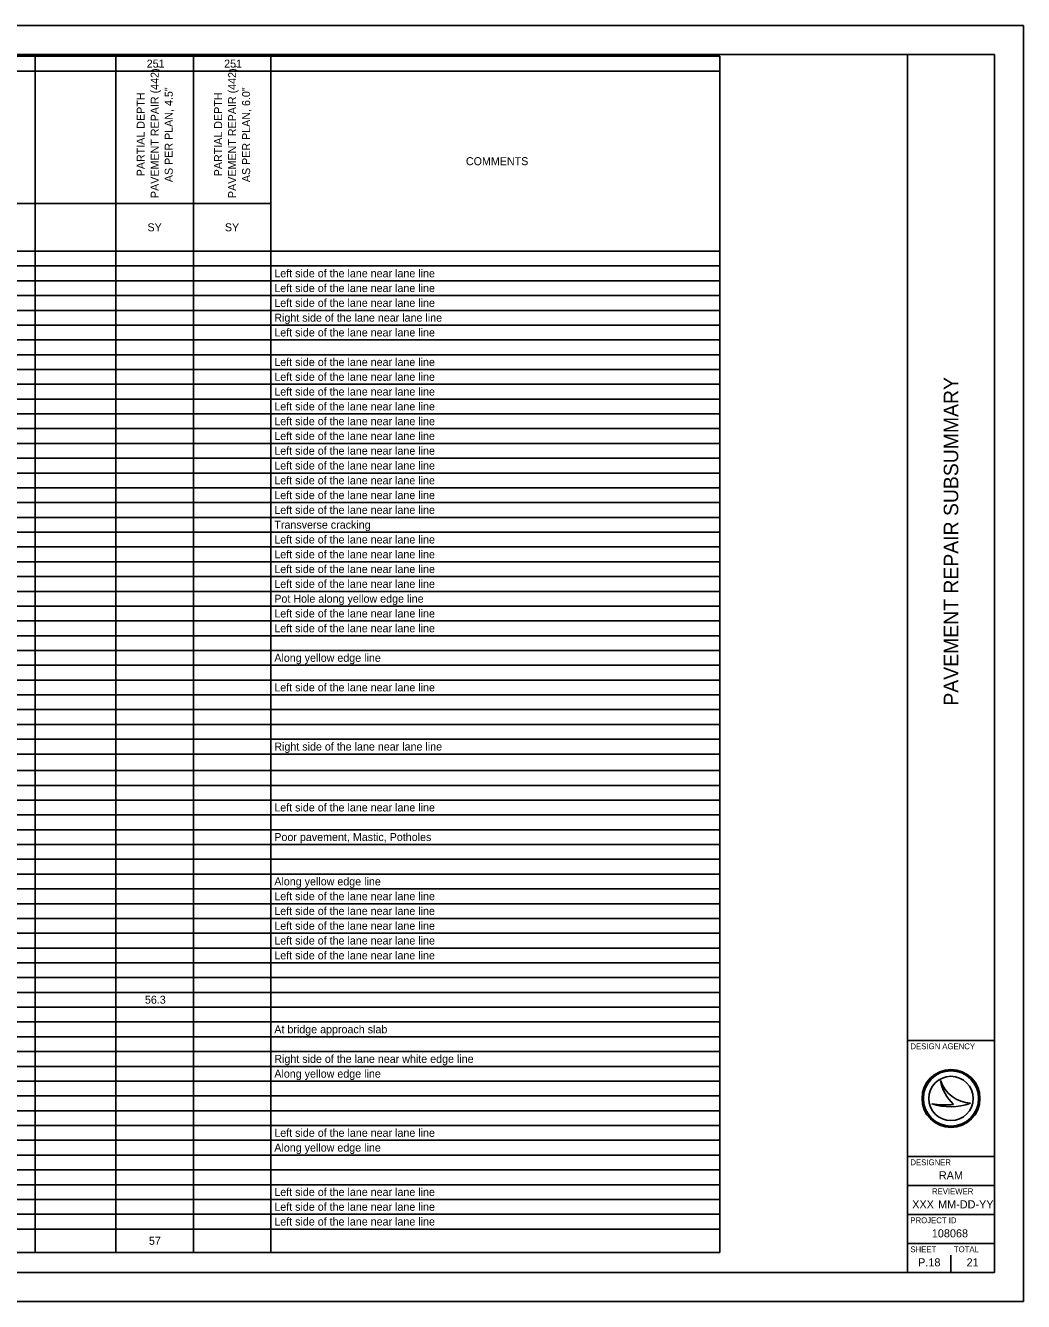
# Model space of a CAD drawing. Extents: x 0 to 34, y 0 to 22.
# Drawn here: x 16.79 to 34, y 0 to 22 of the extents above; entities that cross this region are included whole.
import ezdxf

# ---------------------------------------------------------------- set-up
doc = ezdxf.new("R2010")
doc.units = 0
for name, color, linetype in [('Default', 7, 'Continuous'), ('SH_Border', 7, 'Continuous'), ('SH_Cut_Line', 7, 'Continuous'), ('SH_Data', 7, 'Continuous')]:
    doc.layers.add(name, color=color, linetype=linetype)

msp = doc.modelspace()

# ---------------------------------------------------------------- linework, layer by layer
at = {"layer": 'Default'}
for p, q in [((4.701, 21.469), (28.761, 21.469)), ((16.956, 21.469), (16.956, 0.844)), ((18.351, 21.469), (18.351, 0.844)), ((19.686, 21.469), (19.686, 0.844)), ((21.021, 21.469), (21.021, 0.844)), ((28.761, 21.469), (28.761, 0.844)), ((4.701, 21.214), (28.761, 21.214)), ((7.806, 18.934), (21.021, 18.934)), ((4.701, 18.109), (28.761, 18.109)), ((4.701, 17.854), (28.761, 17.854)), ((4.701, 17.599), (28.761, 17.599)), ((4.701, 17.344), (28.761, 17.344)), ((4.701, 17.089), (28.761, 17.089)), ((4.701, 16.834), (28.761, 16.834)), ((4.701, 16.579), (28.761, 16.579)), ((4.701, 16.324), (28.761, 16.324)), ((4.701, 16.069), (28.761, 16.069)), ((4.701, 15.814), (28.761, 15.814)), ((4.701, 15.559), (28.761, 15.559)), ((4.701, 15.304), (28.761, 15.304)), ((4.701, 15.049), (28.761, 15.049)), ((4.701, 14.794), (28.761, 14.794)), ((4.701, 14.539), (28.761, 14.539)), ((4.701, 14.284), (28.761, 14.284)), ((4.701, 14.029), (28.761, 14.029)), ((4.701, 13.774), (28.761, 13.774)), ((4.701, 13.519), (28.761, 13.519)), ((4.701, 13.264), (28.761, 13.264)), ((4.701, 13.009), (28.761, 13.009)), ((4.701, 12.754), (28.761, 12.754)), ((4.701, 12.499), (28.761, 12.499)), ((4.701, 12.244), (28.761, 12.244)), ((4.701, 11.989), (28.761, 11.989)), ((4.701, 11.734), (28.761, 11.734)), ((4.701, 11.479), (28.761, 11.479)), ((4.701, 11.224), (28.761, 11.224)), ((4.701, 10.969), (28.761, 10.969)), ((4.701, 10.714), (28.761, 10.714)), ((4.701, 10.459), (28.761, 10.459)), ((4.701, 10.204), (28.761, 10.204)), ((4.701, 9.949), (28.761, 9.949)), ((4.701, 9.694), (28.761, 9.694)), ((4.701, 9.439), (28.761, 9.439)), ((4.701, 9.154), (28.761, 9.154)), ((4.701, 8.899), (28.761, 8.899)), ((4.701, 8.644), (28.761, 8.644)), ((4.701, 8.389), (28.761, 8.389)), ((4.701, 8.134), (28.761, 8.134)), ((4.701, 7.879), (28.761, 7.879)), ((4.701, 7.624), (28.761, 7.624)), ((4.701, 7.369), (28.761, 7.369)), ((4.701, 7.114), (28.761, 7.114)), ((4.701, 6.859), (28.761, 6.859)), ((4.701, 6.604), (28.761, 6.604)), ((4.701, 6.349), (28.761, 6.349)), ((4.701, 6.094), (28.761, 6.094)), ((4.701, 5.839), (28.761, 5.839)), ((4.701, 5.584), (28.761, 5.584)), ((4.701, 5.329), (28.761, 5.329)), ((4.701, 5.074), (28.761, 5.074)), ((4.701, 4.819), (28.761, 4.819)), ((4.701, 4.564), (28.761, 4.564)), ((4.701, 4.309), (28.761, 4.309)), ((4.701, 4.054), (28.761, 4.054)), ((4.701, 3.799), (28.761, 3.799)), ((4.701, 3.544), (28.761, 3.544)), ((4.701, 3.289), (28.761, 3.289)), ((4.701, 3.034), (28.761, 3.034)), ((4.701, 2.779), (28.761, 2.779)), ((4.701, 2.524), (28.761, 2.524)), ((4.701, 2.269), (28.761, 2.269)), ((4.701, 2.014), (28.761, 2.014)), ((4.701, 1.759), (28.761, 1.759)), ((4.701, 1.504), (28.761, 1.504)), ((4.701, 1.249), (28.761, 1.249)), ((4.701, 0.844), (28.761, 0.844))]:
    msp.add_line(p, q, dxfattribs=at)
for points in [[(21.021, 14.284), (28.761, 14.284), (28.761, 14.029), (21.021, 14.029)], [(21.021, 13.519), (28.761, 13.519), (28.761, 13.264), (21.021, 13.264)], [(21.021, 13.264), (28.761, 13.264), (28.761, 13.009), (21.021, 13.009)], [(21.021, 13.009), (28.761, 13.009), (28.761, 12.754), (21.021, 12.754)], [(21.021, 12.499), (28.761, 12.499), (28.761, 12.244), (21.021, 12.244)], [(21.021, 12.244), (28.761, 12.244), (28.761, 11.989), (21.021, 11.989)], [(21.021, 11.989), (28.761, 11.989), (28.761, 11.734), (21.021, 11.734)], [(21.021, 11.734), (28.761, 11.734), (28.761, 11.479), (21.021, 11.479)], [(21.021, 11.479), (28.761, 11.479), (28.761, 11.224), (21.021, 11.224)], [(21.021, 11.224), (28.761, 11.224), (28.761, 10.969), (21.021, 10.969)], [(21.021, 10.714), (28.761, 10.714), (28.761, 10.459), (21.021, 10.459)], [(21.021, 10.459), (28.761, 10.459), (28.761, 10.204), (21.021, 10.204)], [(21.021, 10.204), (28.761, 10.204), (28.761, 9.949), (21.021, 9.949)], [(21.021, 9.949), (28.761, 9.949), (28.761, 9.694), (21.021, 9.694)], [(21.021, 9.694), (28.761, 9.694), (28.761, 9.439), (21.021, 9.439)], [(21.021, 9.439), (28.761, 9.439), (28.761, 9.154), (21.021, 9.154)], [(21.021, 8.644), (28.761, 8.644), (28.761, 8.389), (21.021, 8.389)], [(21.021, 8.389), (28.761, 8.389), (28.761, 8.134), (21.021, 8.134)], [(21.021, 8.134), (28.761, 8.134), (28.761, 7.879), (21.021, 7.879)], [(21.021, 7.879), (28.761, 7.879), (28.761, 7.624), (21.021, 7.624)], [(21.021, 7.624), (28.761, 7.624), (28.761, 7.369), (21.021, 7.369)], [(21.021, 7.369), (28.761, 7.369), (28.761, 7.114), (21.021, 7.114)], [(21.021, 7.114), (28.761, 7.114), (28.761, 6.859), (21.021, 6.859)], [(21.021, 6.859), (28.761, 6.859), (28.761, 6.604), (21.021, 6.604)], [(21.021, 6.604), (28.761, 6.604), (28.761, 6.349), (21.021, 6.349)], [(21.021, 6.349), (28.761, 6.349), (28.761, 6.094), (21.021, 6.094)], [(21.021, 6.094), (28.761, 6.094), (28.761, 5.839), (21.021, 5.839)], [(21.021, 5.839), (28.761, 5.839), (28.761, 5.584), (21.021, 5.584)], [(21.021, 5.584), (28.761, 5.584), (28.761, 5.329), (21.021, 5.329)], [(21.021, 5.329), (28.761, 5.329), (28.761, 5.074), (21.021, 5.074)], [(21.021, 5.074), (28.761, 5.074), (28.761, 4.819), (21.021, 4.819)], [(21.021, 4.819), (28.761, 4.819), (28.761, 4.564), (21.021, 4.564)], [(21.021, 4.309), (28.761, 4.309), (28.761, 4.054), (21.021, 4.054)], [(21.021, 4.054), (28.761, 4.054), (28.761, 3.799), (21.021, 3.799)]]:
    msp.add_lwpolyline(points, close=True, dxfattribs=at)
at = {"layer": 'SH_Border'}
for p, q in [((32, 0.5), (32, 21.5)), ((32, 4.5), (33.5, 4.5)), ((32, 2.5), (33.5, 2.5)), ((32, 2), (33.5, 2)), ((32, 1.5), (33.5, 1.5)), ((32, 1), (33.5, 1))]:
    msp.add_line(p, q, dxfattribs=at)
msp.add_lwpolyline([(1.5, 21.5), (33.5, 21.5), (33.5, 0.5), (1.5, 0.5)], close=True, dxfattribs=at)
at = {"layer": 'SH_Cut_Line'}
msp.add_lwpolyline([(0, 0), (34, 0), (34, 22), (0, 22)], close=True, dxfattribs=at)
at = {"layer": 'SH_Data'}
for p, q in [((32.567, 3.81), (32.567, 3.81)), ((32.417, 3.41), (32.417, 3.41)), ((32.75, 3.5), (32.75, 3.5)), ((33.087, 3.419), (33.087, 3.419)), ((32.375, 0.675), (32.375, 0.675)), ((32.75, 0.5), (32.75, 0.8))]:
    msp.add_line(p, q, dxfattribs=at)
for radius in [0.5, 0.477, 0.477, 0.382]:
    msp.add_circle((32.75, 3.5), radius, dxfattribs=at)
for centre, radius, start, end in [((33.116, 3.998), 0.58, 198.9257, 198.9319), ((33.347, 3.97), 0.796, 191.6379, 191.6421), ((33.116, 3.998), 0.58, 198.9319, 267.1657), ((33.347, 3.97), 0.796, 191.6421, 226.0947), ((32.739, 4.37), 1.013, 251.4576, 290.0832), ((32.648, 4.654), 1.266, 259.4964, 259.4995), ((32.739, 4.37), 1.013, 251.4527, 251.4576), ((32.648, 4.654), 1.266, 259.4995, 276.6672)]:
    msp.add_arc(centre, radius, start, end, dxfattribs=at)

# ---------------------------------------------------------------- texts
at = {"layer": 'Default'}
for s, p in [('251', (18.881, 21.274)), ('251', (20.216, 21.274)), ('COMMENTS', (24.385, 19.592)), ('SY', (18.894, 18.452)), ('SY', (20.229, 18.452)), ('Left side of the lane near lane line', (21.081, 17.659)), ('Left side of the lane near lane line', (21.081, 17.404)), ('Left side of the lane near lane line', (21.081, 17.149)), ('Right side of the lane near lane line', (21.081, 16.894)), ('Left side of the lane near lane line', (21.081, 16.639)), ('Left side of the lane near lane line', (21.081, 16.129)), ('Left side of the lane near lane line', (21.081, 15.874)), ('Left side of the lane near lane line', (21.081, 15.619)), ('Left side of the lane near lane line', (21.081, 15.364)), ('Left side of the lane near lane line', (21.081, 15.109)), ('Left side of the lane near lane line', (21.081, 14.854)), ('Left side of the lane near lane line', (21.081, 14.599)), ('Left side of the lane near lane line', (21.081, 14.344)), ('Left side of the lane near lane line', (21.081, 14.089)), ('Left side of the lane near lane line', (21.081, 13.834)), ('Left side of the lane near lane line', (21.081, 13.579)), ('Transverse cracking', (21.081, 13.324)), ('Left side of the lane near lane line', (21.081, 13.069)), ('Left side of the lane near lane line', (21.081, 12.814)), ('Left side of the lane near lane line', (21.081, 12.559)), ('Left side of the lane near lane line', (21.081, 12.304)), ('Pot Hole along yellow edge line', (21.081, 12.049)), ('Left side of the lane near lane line', (21.081, 11.794)), ('Left side of the lane near lane line', (21.081, 11.539)), ('Along yellow edge line', (21.081, 11.029)), ('Left side of the lane near lane line', (21.081, 10.519)), ('Right side of the lane near lane line', (21.081, 9.499)), ('Left side of the lane near lane line', (21.081, 8.449)), ('Poor pavement, Mastic, Potholes', (21.081, 7.939)), ('Along yellow edge line', (21.081, 7.174)), ('Left side of the lane near lane line', (21.081, 6.919)), ('Left side of the lane near lane line', (21.081, 6.664)), ('Left side of the lane near lane line', (21.081, 6.409)), ('Left side of the lane near lane line', (21.081, 6.154)), ('Left side of the lane near lane line', (21.081, 5.899)), ('56.3', (18.85, 5.134)), ('At bridge approach slab', (21.081, 4.624)), ('Right side of the lane near white edge line', (21.081, 4.114)), ('Along yellow edge line', (21.081, 3.859)), ('Left side of the lane near lane line', (21.081, 2.839)), ('Along yellow edge line', (21.081, 2.584)), ('Left side of the lane near lane line', (21.081, 1.819)), ('Left side of the lane near lane line', (21.081, 1.564)), ('Left side of the lane near lane line', (21.081, 1.309)), ('57', (18.919, 0.977))]:
    msp.add_text(s, height=0.138, dxfattribs=at).set_placement(p)
for s, p in [('PAVEMENT REPAIR (442), ', (19.088, 19.025)), ('PAVEMENT REPAIR (442), ', (20.423, 19.025)), ('AS PER PLAN, 4.5"', (19.329, 19.299)), ('AS PER PLAN, 6.0"', (20.664, 19.299)), ('PARTIAL DEPTH ', (18.846, 19.4)), ('PARTIAL DEPTH ', (20.181, 19.4))]:
    msp.add_text(s, height=0.138, rotation=90, dxfattribs=at).set_placement(p)
at = {"layer": 'SH_Data'}
msp.add_text('PAVEMENT REPAIR SUBSUMMARY', height=0.25, rotation=90, dxfattribs=at).set_placement((32.875, 10.273))
for s, height, p in [('DESIGN AGENCY', 0.1, (32.05, 4.35)), ('DESIGNER', 0.1, (32.05, 2.35)), ('RAM', 0.14, (32.541, 2.105)), ('REVIEWER', 0.1, (32.422, 1.85)), ('XXX', 0.14, (32.081, 1.605)), ('MM-DD-YY', 0.14, (32.527, 1.605)), ('PROJECT ID', 0.1, (32.05, 1.35)), ('108068', 0.14, (32.419, 1.105)), ('SHEET', 0.1, (32.05, 0.85)), ('TOTAL', 0.1, (32.8, 0.85)), ('P.18', 0.14, (32.183, 0.605)), ('21', 0.14, (33.019, 0.605))]:
    msp.add_text(s, height=height, dxfattribs=at).set_placement(p)

doc.saveas('drawing.dxf')
